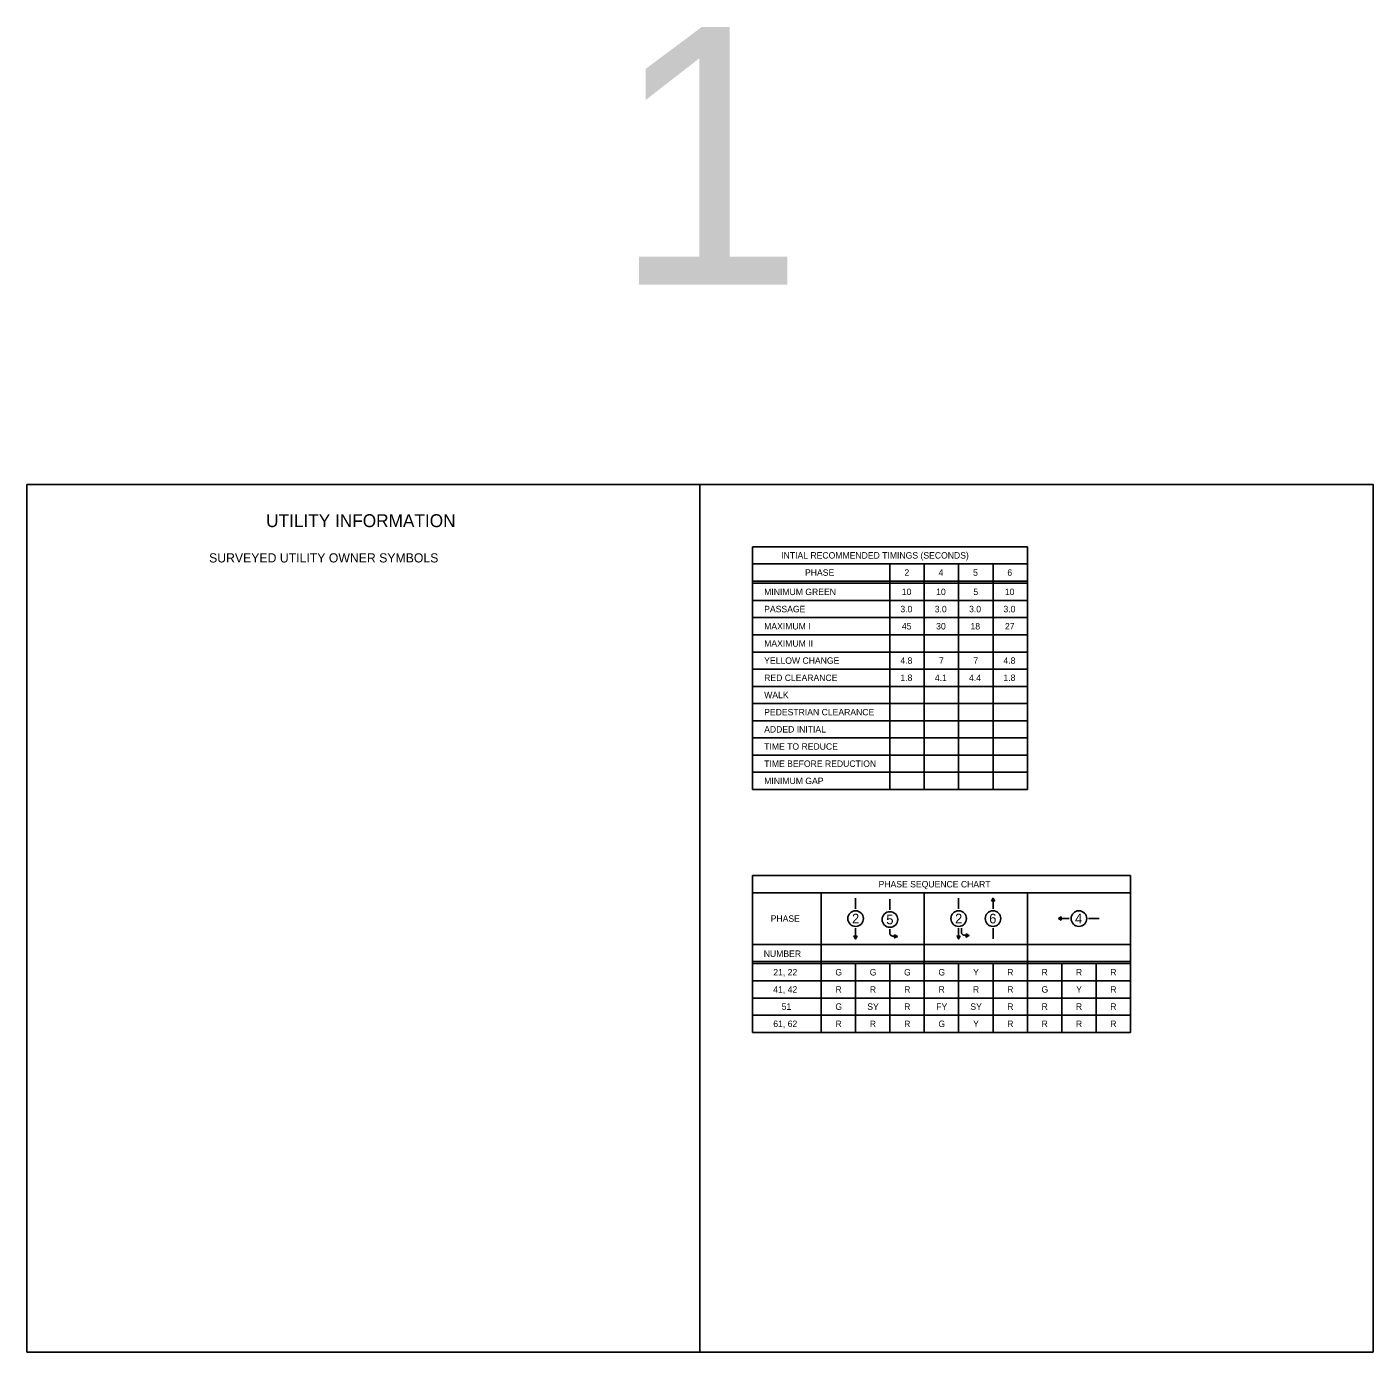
# Model space of a CAD drawing. Extents: x 10133 to 81668, y 7924 to 11018.
# Drawn here: x 10133 to 13268, y 7924 to 11009 of the extents above; entities that cross this region are included whole.
import ezdxf

# ---------------------------------------------------------------- set-up
doc = ezdxf.new("R2010")
doc.units = 0
for name, color, linetype in [('DisROW Survey', 7, 'Continuous'), ('Safety', 7, 'Continuous'), ('SheetBorder', 7, 'Continuous'), ('UtilitiesBelowGround', 7, 'Continuous')]:
    doc.layers.add(name, color=color, linetype=linetype)

msp = doc.modelspace()

# ---------------------------------------------------------------- linework, layer by layer
at = {"layer": 'DisROW Survey'}
msp.add_lwpolyline([(10132.5, 9944), (13267.5, 9944), (13267.5, 7924), (10132.5, 7924)], close=True, dxfattribs=at)
at = {"layer": 'Safety'}
for p, q in [((12062.4, 8955.7), (12062.4, 8980.7)), ((12142.4, 8953.5), (12142.4, 8978.5)), ((12302.4, 8955.7), (12302.4, 8980.7)), ((12382.4, 8955.7), (12382.4, 8980.7)), ((12062.4, 8910.9), (12062.4, 8885.9)), ((12142.4, 8908.8), (12142.4, 8897.1)), ((12302.4, 8910.9), (12302.4, 8885.9)), ((12308.8, 8910.9), (12308.8, 8899.2)), ((12382.4, 8910.9), (12382.4, 8885.9)), ((12560, 8933.3), (12535, 8933.3)), ((12604.8, 8933.3), (12629.8, 8933.3)), ((12062.4, 8885.9), (12058.6, 8892.4)), ((12058.6, 8892.4), (12066.1, 8892.4)), ((12062.4, 8885.9), (12066.1, 8892.4)), ((12302.4, 8885.9), (12298.6, 8892.4)), ((12298.6, 8892.4), (12306.1, 8892.4)), ((12302.4, 8885.9), (12306.1, 8892.4))]:
    msp.add_line(p, q, dxfattribs=at)
for points in [[(12378.6, 8974.2), (12382.4, 8980.7), (12382.4, 8974.2)], [(12382.4, 8980.7), (12386.1, 8974.2), (12382.4, 8974.2)], [(12535, 8933.3), (12541.5, 8937), (12541.5, 8933.3)], [(12541.5, 8929.5), (12535, 8933.3), (12541.5, 8933.3)], [(12062.4, 8885.9), (12058.6, 8892.4), (12062.4, 8892.4)], [(12066.1, 8892.4), (12062.4, 8885.9), (12062.4, 8892.4)], [(12159.7, 8891.8), (12153.2, 8888.1), (12153.3, 8891.9)], [(12153.3, 8895.6), (12159.7, 8891.8), (12153.3, 8891.9)], [(12302.4, 8885.9), (12298.6, 8892.4), (12302.4, 8892.4)], [(12306.1, 8892.4), (12302.4, 8885.9), (12302.4, 8892.4)], [(12326.2, 8893.9), (12319.6, 8890.3), (12319.7, 8894)], [(12319.7, 8897.8), (12326.2, 8893.9), (12319.7, 8894)]]:
    msp.add_lwpolyline(points, close=True, dxfattribs=at)
for centre in [(12062.4, 8933.3), (12142.4, 8931.1), (12302.4, 8933.3), (12382.4, 8933.3), (12582.4, 8933.3)]:
    msp.add_circle(centre, 18.2, dxfattribs=at)
for points in [[(12142.4, 8897.1), (12144.5, 8893.1), (12152.7, 8891.8), (12154.5, 8891.8), (12159.7, 8891.8)], [(12308.8, 8899.2), (12311, 8895.3), (12319.1, 8893.9), (12321, 8893.9), (12326.2, 8893.9)]]:
    msp.add_open_spline(points, degree=2, dxfattribs=at)
at = {"layer": 'SheetBorder'}
for p, q in [((11700, 9944), (11700, 7924)), ((11822.4, 9798.9), (11822.4, 9233.9)), ((11822.4, 9798.9), (12462.4, 9798.9)), ((12462.4, 9798.9), (12462.4, 9233.9)), ((11822.4, 9758.9), (12462.4, 9758.9)), ((12142.4, 9758.9), (12142.4, 9233.9)), ((12222.4, 9758.9), (12222.4, 9233.9)), ((12302.4, 9758.9), (12302.4, 9233.9)), ((12382.4, 9758.9), (12382.4, 9233.9)), ((11822.4, 9718.9), (12462.4, 9718.9)), ((11822.4, 9713.9), (12462.4, 9713.9)), ((11822.4, 9673.9), (12462.4, 9673.9)), ((11822.4, 9633.9), (12462.4, 9633.9)), ((11822.4, 9593.9), (12462.4, 9593.9)), ((11822.4, 9553.9), (12462.4, 9553.9)), ((11822.4, 9513.9), (12462.4, 9513.9)), ((11822.4, 9473.9), (12462.4, 9473.9)), ((11822.4, 9433.9), (12462.4, 9433.9)), ((11822.4, 9393.9), (12462.4, 9393.9)), ((11822.4, 9353.9), (12462.4, 9353.9)), ((11822.4, 9313.9), (12462.4, 9313.9)), ((11822.4, 9273.9), (12462.4, 9273.9)), ((11822.4, 9233.9), (12462.4, 9233.9)), ((11822.4, 9033.3), (11822.4, 8668.3)), ((11822.4, 9033.3), (12702.4, 9033.3)), ((12702.4, 9033.3), (12702.4, 8668.3)), ((11822.4, 8993.3), (12702.4, 8993.3)), ((11982.4, 8993.3), (11982.4, 8668.3)), ((12222.4, 8993.3), (12222.4, 8668.3)), ((12462.4, 8993.3), (12462.4, 8668.3)), ((11822.4, 8873.3), (12702.4, 8873.3)), ((11822.4, 8833.3), (12702.4, 8833.3)), ((11822.4, 8828.3), (12702.4, 8828.3)), ((12062.4, 8828.3), (12062.4, 8668.3)), ((12142.4, 8828.3), (12142.4, 8668.3)), ((12302.4, 8828.3), (12302.4, 8668.3)), ((12382.4, 8828.3), (12382.4, 8668.3)), ((12542.4, 8828.3), (12542.4, 8668.3)), ((12622.4, 8828.3), (12622.4, 8668.3)), ((11822.4, 8788.3), (12702.4, 8788.3)), ((11822.4, 8788.3), (12702.4, 8788.3)), ((11822.4, 8748.3), (12702.4, 8748.3)), ((11822.4, 8708.3), (12702.4, 8708.3)), ((11822.4, 8668.3), (12702.4, 8668.3))]:
    msp.add_line(p, q, dxfattribs=at)

# ---------------------------------------------------------------- texts
at = {"layer": 'Safety'}
for s, height, p in [('1', 600, (11496.6, 10409.2)), ('INTIAL RECOMMENDED TIMINGS (SECONDS)', 15, (11889.2, 9771.4)), ('PHASE', 15, (11944.6, 9731.4)), ('2', 15, (12176.1, 9731.4)), ('4', 15, (12255.7, 9731.4)), ('5', 15, (12336, 9731.4)), ('6', 15, (12415.8, 9731.4)), ('10', 15, (12170, 9686.4)), ('10', 15, (12250, 9686.4)), ('5', 15, (12336.7, 9686.4)), ('10', 15, (12410, 9686.4)), ('3.0', 15, (12166.7, 9646.4)), ('3.0', 15, (12246.7, 9646.4)), ('3.0', 15, (12326.7, 9646.4)), ('3.0', 15, (12406.7, 9646.4)), ('45', 15, (12170.2, 9606.4)), ('30', 15, (12250, 9606.4)), ('18', 15, (12330, 9606.4)), ('27', 15, (12410.2, 9606.4)), ('4.8', 15, (12166.7, 9526.4)), ('7', 15, (12256.7, 9526.4)), ('7', 15, (12336.7, 9526.4)), ('4.8', 15, (12406.7, 9526.4)), ('1.8', 15, (12166.7, 9486.4)), ('4.1', 15, (12247, 9486.4)), ('4.4', 15, (12326.6, 9486.4)), ('1.8', 15, (12406.7, 9486.4)), ('PHASE SEQUENCE CHART', 15, (12115.9, 9005.8)), ('PHASE', 15, (11864.6, 8925.8)), ('2', 22.5, (12054.1, 8922)), ('5', 22.5, (12133.9, 8919.9)), ('2', 22.5, (12294.1, 8922)), ('6', 22.5, (12373.5, 8922)), ('4', 22.5, (12573.4, 8922)), ('NUMBER', 15, (11848.5, 8844)), ('21, 22', 15, (11870.7, 8800.8)), ('G', 15, (12015.3, 8800.8)), ('G', 15, (12095.3, 8800.8)), ('G', 15, (12175.3, 8800.8)), ('G', 15, (12255.3, 8800.8)), ('Y', 15, (12336.1, 8800.8)), ('R', 15, (12415.5, 8800.8)), ('R', 15, (12495.5, 8800.8)), ('R', 15, (12575.5, 8800.8)), ('R', 15, (12655.5, 8800.8)), ('41, 42', 15, (11870.7, 8760.8)), ('R', 15, (12015.5, 8760.8)), ('R', 15, (12095.5, 8760.8)), ('R', 15, (12175.5, 8760.8)), ('R', 15, (12255.5, 8760.8)), ('R', 15, (12335.5, 8760.8)), ('R', 15, (12415.5, 8760.8)), ('G', 15, (12495.3, 8760.8)), ('Y', 15, (12576.1, 8760.8)), ('R', 15, (12655.5, 8760.8)), ('51', 15, (11890.3, 8720.8)), ('G', 15, (12015.3, 8720.8)), ('SY', 15, (12089.6, 8720.8)), ('R', 15, (12175.5, 8720.8)), ('FY', 15, (12250.2, 8720.8)), ('SY', 15, (12329.6, 8720.8)), ('R', 15, (12415.5, 8720.8)), ('R', 15, (12495.5, 8720.8)), ('R', 15, (12575.5, 8720.8)), ('R', 15, (12655.5, 8720.8)), ('61, 62', 15, (11870.7, 8680.8)), ('R', 15, (12015.5, 8680.8)), ('R', 15, (12095.5, 8680.8)), ('R', 15, (12175.5, 8680.8)), ('G', 15, (12255.3, 8680.8)), ('Y', 15, (12336.1, 8680.8)), ('R', 15, (12415.5, 8680.8)), ('R', 15, (12495.5, 8680.8)), ('R', 15, (12575.5, 8680.8)), ('R', 15, (12655.5, 8680.8))]:
    msp.add_text(s, height=height, dxfattribs=at).set_placement(p)
at = {"layer": 'SheetBorder'}
for s, height, p in [('UTILITY INFORMATION', 30, (10689.5, 9844.7)), ('MINIMUM GREEN', 15, (11849.5, 9686.4)), ('PASSAGE', 15, (11849.5, 9646.4)), ('MAXIMUM I', 15, (11849.5, 9606.4)), ('MAXIMUM II', 15, (11849.5, 9566.4)), ('YELLOW CHANGE', 15, (11849.5, 9526.4)), ('RED CLEARANCE', 15, (11849.5, 9486.4)), ('WALK', 15, (11849.5, 9446.4)), ('PEDESTRIAN CLEARANCE', 15, (11849.5, 9406.4)), ('ADDED INITIAL', 15, (11849.5, 9366.4)), ('TIME TO REDUCE', 15, (11849.5, 9326.4)), ('TIME BEFORE REDUCTION', 15, (11849.5, 9286.4)), ('MINIMUM GAP', 15, (11849.5, 9246.4))]:
    msp.add_text(s, height=height, dxfattribs=at).set_placement(p)
at = {"layer": 'UtilitiesBelowGround'}
msp.add_text('SURVEYED UTILITY OWNER SYMBOLS', height=21.328, dxfattribs=at).set_placement((10556.7, 9762.4))

doc.saveas('drawing.dxf')
